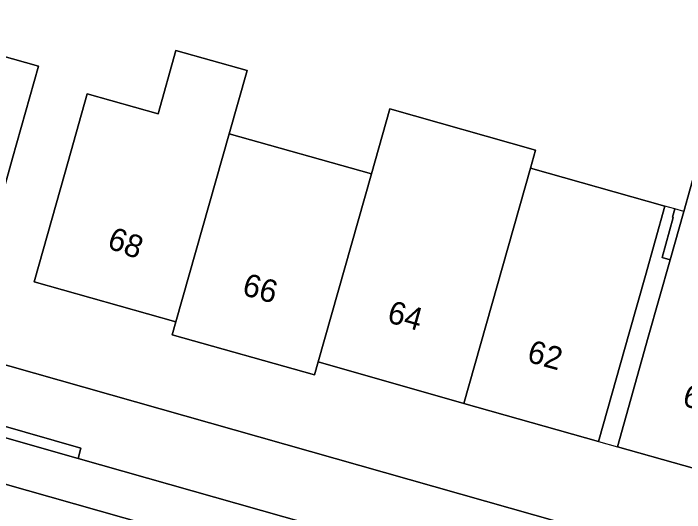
# Model space of a CAD drawing. Extents: x 158086 to 159499, y 382904 to 383981.
# Drawn here: x 158766.64 to 158796.14, y 383323.61 to 383345.54 of the extents above; entities that cross this region are included whole.
import ezdxf

# ---------------------------------------------------------------- set-up
doc = ezdxf.new("R2010")
doc.units = 0
for name, color, linetype in [('IMGEO_Erf', 7, 'Continuous'), ('IMGEO_Pand', 7, 'Continuous'), ('IMGEO_Pand_nummerreeks', 7, 'Continuous'), ('IMGEO_Pand_overbouw', 7, 'Continuous'), ('IMGEO_Parkeervlak_open', 7, 'Continuous'), ('IMGEO_Rijbaan_lokaal_gesloten', 7, 'Continuous'), ('IMGEO_Voetpad_open', 7, 'Continuous')]:
    doc.layers.add(name, color=color, linetype=linetype)

msp = doc.modelspace()

# ---------------------------------------------------------------- linework, layer by layer
at = {"layer": 'IMGEO_Erf'}
msp.add_lwpolyline([(158762.697, 383346.875), (158762.113, 383344.8), (158767.736, 383343.218), (158766.601, 383339.181), (158765.246, 383334.367), (158759.623, 383335.949), (158754.092, 383337.505), (158748.536, 383339.068), (158742.718, 383340.705), (158741.709, 383337.068), (158766.48, 383330.042), (158829.102, 383312.279)], dxfattribs=at)
for points in [[(158795.275, 383337.065), (158794.417, 383334.026), (158793.716, 383331.543), (158792.358, 383326.73), (158786.442, 383328.399), (158780.03, 383330.222), (158779.87, 383329.658), (158773.622, 383331.416), (158773.784, 383331.992), (158767.556, 383333.744), (158768.91, 383338.558), (158769.881, 383342.009), (158773.003, 383341.131), (158773.783, 383343.901), (158776.91, 383343.021), (158776.125, 383340.252), (158782.376, 383338.493), (158783.184, 383341.341), (158789.594, 383339.523), (158789.371, 383338.737)], [(158796.667, 383338.829), (158802.405, 383337.209), (158801.027, 383332.166), (158800.345, 383329.671), (158799.027, 383324.847), (158793.186, 383326.496), (158794.544, 383331.309), (158795.506, 383334.714), (158796.106, 383336.84)]]:
    msp.add_lwpolyline(points, close=True, dxfattribs=at)
at = {"layer": 'IMGEO_Pand'}
for points in [[(158759.623, 383335.949), (158765.246, 383334.367), (158766.601, 383339.181), (158767.736, 383343.218), (158762.113, 383344.8)], [(158776.125, 383340.252), (158776.91, 383343.021), (158773.783, 383343.901), (158773.003, 383341.131), (158769.881, 383342.009), (158768.91, 383338.558), (158767.556, 383333.744), (158773.784, 383331.992)], [(158780.03, 383330.222), (158786.442, 383328.399), (158789.371, 383338.737), (158789.594, 383339.523), (158783.184, 383341.341), (158782.376, 383338.493)], [(158782.376, 383338.493), (158776.125, 383340.252), (158773.784, 383331.992), (158773.622, 383331.416), (158779.87, 383329.658), (158780.03, 383330.222)], [(158789.371, 383338.737), (158786.442, 383328.399), (158792.358, 383326.73), (158793.716, 383331.543), (158794.417, 383334.026), (158795.275, 383337.065)], [(158796.106, 383336.84), (158795.506, 383334.714), (158794.544, 383331.309), (158793.186, 383326.496), (158799.027, 383324.847), (158800.345, 383329.671), (158801.027, 383332.166), (158802.405, 383337.209), (158796.667, 383338.829)]]:
    msp.add_lwpolyline(points, close=True, dxfattribs=at)
at = {"layer": 'IMGEO_Pand_overbouw'}
for points in [[(158795.506, 383334.714), (158795.149, 383334.814), (158795.646, 383336.575), (158795.613, 383336.584), (158795.715, 383336.946), (158795.275, 383337.065), (158794.417, 383334.026), (158793.716, 383331.543), (158792.358, 383326.73), (158793.186, 383326.496), (158794.544, 383331.309)], [(158795.715, 383336.946), (158795.613, 383336.584), (158795.646, 383336.575), (158795.149, 383334.814), (158795.506, 383334.714), (158796.106, 383336.84)]]:
    msp.add_lwpolyline(points, close=True, dxfattribs=at)
at = {"layer": 'IMGEO_Parkeervlak_open'}
for points in [[(158769.481, 383325.984), (158765.619, 383327.078), (158744.994, 383332.925), (158744.303, 383332.843), (158742.912, 383332.164)], [(158741.506, 383331.88), (158765.072, 383325.196), (158890.262, 383289.69), (158944.658, 383274.49)], [(158942.057, 383277.301), (158890.831, 383291.584), (158769.481, 383325.984)]]:
    msp.add_lwpolyline(points, dxfattribs=at)
at = {"layer": 'IMGEO_Rijbaan_lokaal_gesloten'}
msp.add_lwpolyline([(158890.262, 383289.69), (158765.072, 383325.196), (158741.506, 383331.88), (158740.417, 383328.436), (158759.428, 383323.022), (158764.06, 383321.713), (158775.977, 383318.346), (158777.269, 383318.018), (158793.787, 383313.278), (158796.136, 383312.583), (158796.541, 383312.469), (158829.722, 383303.087), (158829.74, 383303.082), (158829.758, 383303.076), (158834.805, 383301.617), (158836.836, 383301.132), (158874.937, 383290.272), (158883.066, 383288.015), (158884.054, 383287.741)], dxfattribs=at)
at = {"layer": 'IMGEO_Voetpad_open'}
for points in [[(158909.214, 383289.555), (158830.055, 383312.009), (158829.102, 383312.279), (158766.48, 383330.042), (158741.709, 383337.068), (158733.649, 383339.682)], [(158742.912, 383332.164), (158744.303, 383332.843), (158744.994, 383332.925), (158765.619, 383327.078), (158765.751, 383327.533), (158765.966, 383327.472), (158769.605, 383326.437), (158769.481, 383325.984), (158890.831, 383291.584), (158942.057, 383277.301)]]:
    msp.add_lwpolyline(points, dxfattribs=at)
msp.add_lwpolyline([(158765.619, 383327.078), (158769.481, 383325.984), (158769.605, 383326.437), (158765.966, 383327.472), (158765.751, 383327.533)], close=True, dxfattribs=at)

# ---------------------------------------------------------------- texts
at = {"layer": 'IMGEO_Pand_nummerreeks'}
for s, rotation, p in [('68', 339.4423, (158770.709, 383335.252)), ('66', 344.2838, (158776.646, 383333.183)), ('64', 344.243, (158783.019, 383331.983)), ('62', 344.243, (158789.168, 383330.248)), ('60', 344.2322, (158795.999, 383328.32))]:
    msp.add_text(s, height=1, rotation=rotation, dxfattribs=at).set_placement(p)

doc.saveas('drawing.dxf')
